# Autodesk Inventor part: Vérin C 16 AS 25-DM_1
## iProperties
Shininess: 20.0
Angle Display Precision: 2
Document Length Units: 11269
Document Angle Units: 11279
Document Time Units: 11290
Document Mass Units: 11283
Document Length Units Precision: 3
Document Angle Units Precision: 2
Created: 2002-02
Part Number: Vérin C 16 AS 25-DM_1
Material: Par défaut
Document SubType Name: Modélisation
Designer: Administrateur
Density: 0.0
Volumn: 0.0
Area: 0.0
PropertySet Name: Model Information
Control State: 0
Master: False
Checked Out: False
Author: Administrateur
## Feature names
1. Base1
